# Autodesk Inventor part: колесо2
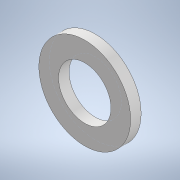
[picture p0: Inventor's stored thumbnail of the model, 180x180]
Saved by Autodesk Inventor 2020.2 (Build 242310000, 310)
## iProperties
Created: 2020-04
Part Number: колесо2
Material: Типовые
Document SubType Name: Modeling
Designer: Алексей
Density: 1 g/cm^3
Appearance: По умолчанию
Author: Алексей
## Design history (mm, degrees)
sketch "Эскиз1"
  geometry: C1 r 17.5 at (0, 0); C2 r 10 at (0, 0); 1 further point
  constraints: 2 centre point, 2 coincident
  dimensions: "d0" = 35 diameter of C1; "d1" = 20 diameter of C2
extrude "Выдавливание1" new body sketch "Эскиз1" distance "d2" = 4; taper "d3" = 0 deg
node "Твердое тело1"
